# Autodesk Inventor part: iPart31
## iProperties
Created: 2005-03
Part Number: iPart31
Document SubType Name: Modeling
Designer: CADCIM
Manufacturer: Standard
Standards Organization: Custom
Author: CADCIM
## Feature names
1. Derived Body1 [Tagging]
